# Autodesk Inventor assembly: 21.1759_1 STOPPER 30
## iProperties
Created: 2007-03
Part Number: 21.1759_1 STOPPER 30
Document SubType Name: Assembly
Designer: Andy Moles
Mass: 24.2738 g
Surface Area: 50.9772 cm^2
Volume: 22.3168 cm^3
Density: 1.08769 g/cm^3
Author: Andy Moles
